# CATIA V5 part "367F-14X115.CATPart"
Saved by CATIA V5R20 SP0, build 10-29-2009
Part number: 367F-14X115
Definition: NONE
Nomenclature: 367F-14X115
Source: Unknown
Description: 367F-14X115
Bounding box of the stored display mesh (mm): x 0 to 115, y -14 to 14, z -14 to 14
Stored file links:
  C:\Users\Utente\Desktop\IO LAVORO\3D X SITO CF\X SITO\PLASTICA\3D files 367\367F-14X115.CATPart
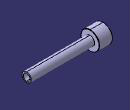
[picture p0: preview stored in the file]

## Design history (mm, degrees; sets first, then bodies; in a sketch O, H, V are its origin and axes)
Body1 "367F-14X115" (main body)
  Solid1: solid without history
